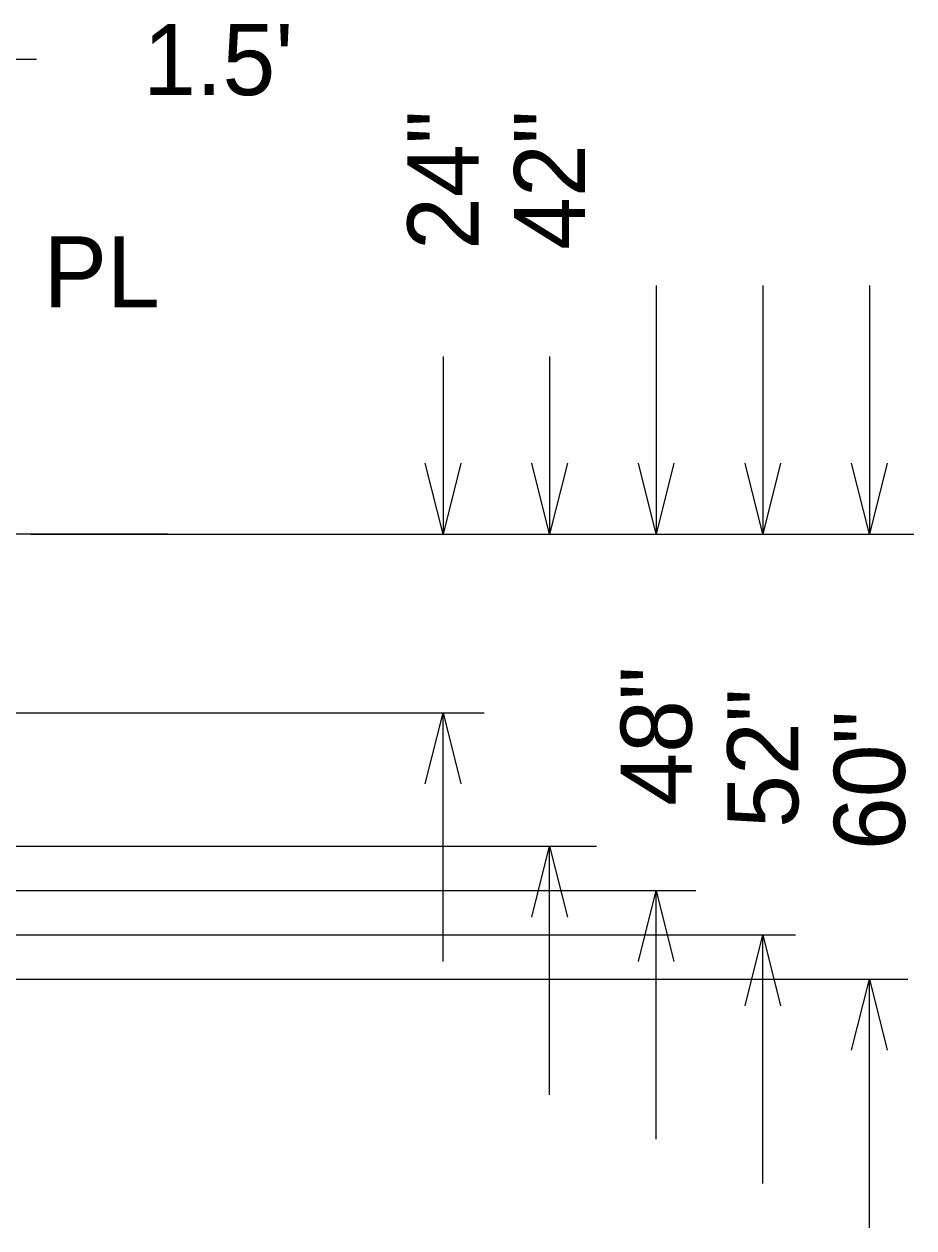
# Model space of a CAD drawing. Extents: x 524397 to 525117, y 3701341 to 3701821.
# Drawn here: x 524607.59 to 524627.64, y 3701673.43 to 3701700.55 of the extents above; entities that cross this region are included whole.
import ezdxf

# ---------------------------------------------------------------- set-up
doc = ezdxf.new("R2010")
doc.units = 0
doc.layers.add('Level 11', color=7, linetype='Continuous')

msp = doc.modelspace()

# ---------------------------------------------------------------- linework, layer by layer
at = {"layer": 'Level 11'}
for p, q in [((524607.874, 3701699.754), (524603.871, 3701699.754)), ((524621.833, 3701694.666), (524621.833, 3701689.063)), ((524624.234, 3701694.666), (524624.234, 3701689.063)), ((524626.635, 3701694.666), (524626.635, 3701689.063)), ((524617.03, 3701693.065), (524617.03, 3701689.063)), ((524619.431, 3701693.065), (524619.431, 3701689.063)), ((524617.03, 3701689.063), (524616.63, 3701690.664)), ((524617.43, 3701690.664), (524617.03, 3701689.063)), ((524619.431, 3701689.063), (524619.031, 3701690.664)), ((524619.831, 3701690.664), (524619.431, 3701689.063)), ((524621.833, 3701689.063), (524621.432, 3701690.664)), ((524622.233, 3701690.664), (524621.833, 3701689.063)), ((524624.234, 3701689.063), (524623.834, 3701690.664)), ((524624.634, 3701690.664), (524624.234, 3701689.063)), ((524626.635, 3701689.063), (524626.235, 3701690.664)), ((524627.036, 3701690.664), (524626.635, 3701689.063)), ((524610.833, 3701689.063), (524604.887, 3701689.063)), ((524607.741, 3701689.063), (524610.165, 3701689.063)), ((524608.858, 3701689.063), (524616.427, 3701689.063)), ((524608.858, 3701689.063), (524618.829, 3701689.063)), ((524608.858, 3701689.063), (524621.23, 3701689.063)), ((524608.858, 3701689.063), (524623.632, 3701689.063)), ((524608.858, 3701689.063), (524627.639, 3701689.063)), ((524610.119, 3701689.063), (524611.711, 3701689.063)), ((524610.754, 3701689.063), (524613.258, 3701689.063)), ((524587.671, 3701685.033), (524617.96, 3701685.033)), ((524616.63, 3701683.432), (524617.03, 3701685.033)), ((524617.03, 3701679.429), (524617.03, 3701685.033)), ((524617.03, 3701685.033), (524617.43, 3701683.432)), ((524589.671, 3701682.033), (524620.485, 3701682.033)), ((524619.031, 3701680.432), (524619.431, 3701682.033)), ((524619.431, 3701676.429), (524619.431, 3701682.033)), ((524619.431, 3701682.033), (524619.831, 3701680.432)), ((524589.671, 3701681.033), (524622.729, 3701681.033)), ((524621.432, 3701679.432), (524621.833, 3701681.033)), ((524621.833, 3701675.429), (524621.833, 3701681.033)), ((524621.833, 3701681.033), (524622.233, 3701679.432)), ((524589.671, 3701680.033), (524624.974, 3701680.033)), ((524623.834, 3701678.432), (524624.234, 3701680.033)), ((524624.234, 3701674.429), (524624.234, 3701680.033)), ((524624.234, 3701680.033), (524624.634, 3701678.432)), ((524589.671, 3701679.033), (524627.499, 3701679.033)), ((524626.235, 3701677.432), (524626.635, 3701679.033)), ((524626.635, 3701673.429), (524626.635, 3701679.033)), ((524626.635, 3701679.033), (524627.036, 3701677.432))]:
    msp.add_line(p, q, dxfattribs=at)

# ---------------------------------------------------------------- texts
for s, p in [("1.5'", (524610.275, 3701698.953)), ('PL', (524608.032, 3701694.17))]:
    msp.add_text(s, height=1.601, dxfattribs=at).set_placement(p)
for s, p in [('24"', (524617.83, 3701695.466)), ('42"', (524620.232, 3701695.466)), ('48"', (524622.633, 3701682.942)), ('52"', (524625.034, 3701682.442)), ('60"', (524627.436, 3701681.942))]:
    msp.add_text(s, height=1.601, rotation=90, dxfattribs=at).set_placement(p)

doc.saveas('drawing.dxf')
